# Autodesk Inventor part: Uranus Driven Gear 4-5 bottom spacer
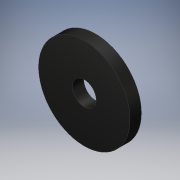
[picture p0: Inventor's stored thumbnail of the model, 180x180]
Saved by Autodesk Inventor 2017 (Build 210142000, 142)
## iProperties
Created: 2017-05
Part Number: Uranus Driven Gear 4-5 bottom spacer
Material: Generic
Document SubType Name: Modeling
Designer: Stan
Density: 1 g/cm^3
Appearance: Glossy - Black
Author: Stan
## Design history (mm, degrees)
sketch "Sketch1"
  geometry: C1 r 3.302 at (0, 0); C2 r 12.7 at (0, 0); 1 further point
  constraints: 2 centre point, 2 coincident
  dimensions: "d0" = 6.604 diameter of C1; "d1" = 25.4 diameter of C2
extrude "Extrusion1" new body sketch "Sketch1" distance "d2" = 3.175; taper "d3" = 0 deg
body "Solid1"
